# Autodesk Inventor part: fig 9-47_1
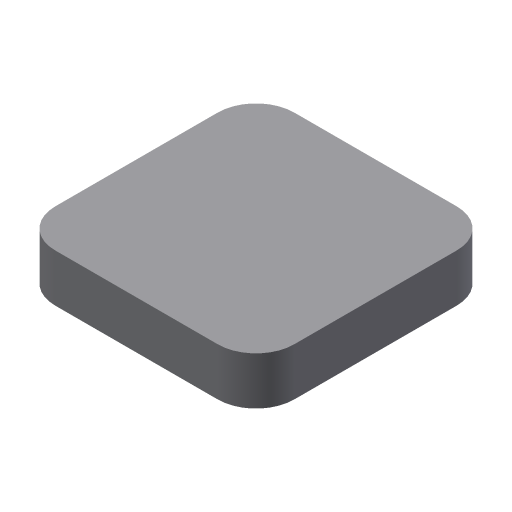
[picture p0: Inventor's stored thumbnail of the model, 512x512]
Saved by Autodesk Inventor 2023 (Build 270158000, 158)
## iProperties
Created: 2013-03
Part Number: fig 9-47_1
Material: Generic
Document SubType Name: Modeling
Designer: CADCIM
Density: 1 g/cm^3
Appearance: Default
Author: CADCIM
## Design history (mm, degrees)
sketch "Sketch1"
  geometry: L1 (-12.5, 12.5)-(12.5, 12.5); L2 (12.5, 12.5)-(12.5, -12.5); L3 (12.5, -12.5)-(-12.5, -12.5); L4 (-12.5, -12.5)-(-12.5, 12.5); 1 further point
  constraints: 8 end point, 2 parallel, 1 horizontal, 1 perpendicular
  dimensions: "d0" = 25 distance of L1.start L1.end; "d2" = 25 distance of L1.end L2.end
extrude "Extrusion1" new body sketch "Sketch1" distance "d3" = 5; taper "d4" = 0 deg
fillet "Fillet1" dims "d5" = 4
body "Solid1"
